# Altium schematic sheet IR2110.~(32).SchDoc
size A4
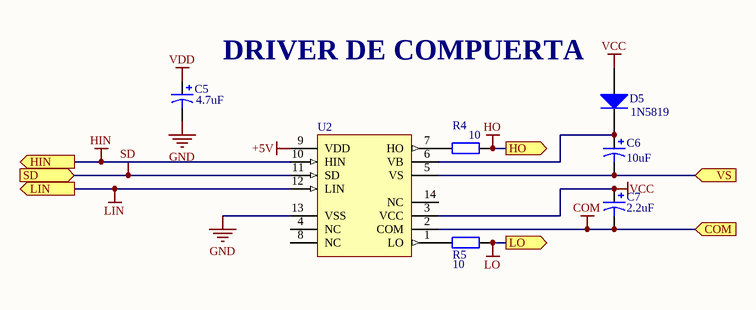
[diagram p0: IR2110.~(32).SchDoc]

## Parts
C5  value 4.7uF  [CAPPR2.5-6.3X5]  (hidden comment: Cap Pol1 4.7u)
C6  value 10uF  [CAPPR2.5-6.3X5]  (hidden comment: Cap Pol1)
C7  value 2.2uF  [CAPPR2.5-6.3X5]  (hidden comment: Cap Pol1)
D5  value 1N5819  [DO-204AL]  (hidden comment: Diode)
R4  10  [AXIAL-0.3]
R5  10  [AXIAL-0.3]
U2  IR2110  [PDIP14]  (value not drawn)

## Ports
COM (in), HIN (out), HO (out), LIN (out), LO (out), SD (in), VS (in)

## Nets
+5V: U2.9(VDD)
COM: C7.2 U2.2(COM) ; port COM
GND: C5.2 U2.13(VSS)
HIN: U2.10(HIN) ; port HIN
HO: R4.2 ; port HO
LIN: U2.12(LIN) ; port LIN
LO: R5.2 ; port LO
SD: U2.11(SD) ; port SD
VCC: C7.1 D5.1(A) U2.3(VCC)
VDD: C5.1
VS: C6.2 U2.5(VS) ; port VS
NetC6_1: C6.1 D5.2(K) U2.6(VB)
NetR4_1: R4.1 U2.7(HO)
NetR5_1: R5.1 U2.1(LO)

Not connected (* = marked no-connect by the designer): U2 4(NC) 8(NC) 14(NC)

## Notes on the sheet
- (near C5) DRIVER DE COMPUERTA

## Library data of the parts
C5-C7 = Cap Pol1: Polarized Capacitor (Radial)
D5 = Diode: 1N5819
R4 R5 = Res2: Resistor
U2 = IR2110: High and Low Side Driver; Note: Pins 4, 8 and 14 are not connected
